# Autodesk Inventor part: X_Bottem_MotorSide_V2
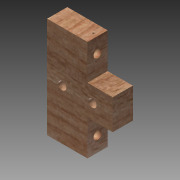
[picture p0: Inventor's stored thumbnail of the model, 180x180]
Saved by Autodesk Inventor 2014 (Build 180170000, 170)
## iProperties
Created: 2013-12
Part Number: X_Bottem_MotorSide_V2
Material: Birch
Document SubType Name: Modeling
Designer: Bram
Density: 0.512 g/cm^3
Appearance: Birch - Natural Medium Gloss
Author: Bram
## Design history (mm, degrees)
sketch "Sketch1"
  geometry: L1 (0, 0)-(60, 0); L2 (60, 0)-(60, 100); L3 (60, 100)-(0, 100); L4 (0, 100)-(0, 0); C1 r 4 at (15, 50); C2 r 4 at (45, 50)
  constraints: 8 end point, 2 centre point, 2 parallel, 1 horizontal, 1 perpendicular
  dimensions: "d0" = 60 distance of L3.end L2.end; "d1" = 100 distance of L2.end L1.end; "d4" = 8 diameter of C1; "d5" = 8 diameter of C2
extrude "Extrusion1" new body sketch "Sketch1" distance "d6" = 20; taper "d7" = 0 deg
sketch "Sketch2"
  geometry: L1 (0, 20)-(100, 20) reference; L2 (0, 0)-(0, 20) reference; L3 (50, 20)-(50, 10); L4 (50, 10)-(85, 10); L5 (50, 10)-(15, 10); C1 r 4 at (15, 10); C2 r 4 at (85, 10)
  constraints: 6 end point, 2 centre point, 2 coincident, 1 collinear, 1 midpoint, 1 parallel, 1 perpendicular
  dimensions: "d8" = 35 distance of L3.end L4.end; "d9" = 35 distance of L3.end L5.end; "d10" = 8 diameter of C1; "d11" = 8 diameter of C2
extrude "Extrusion2" cut sketch "Sketch2" distance "d12" = 80; taper "d13" = 0 deg
sketch "Sketch3"
  geometry: L1 (0, 0)-(100, 0) reference; L2 (100, 0)-(100, 20) reference; L3 (0, 20)-(100, 20) reference; L4 (0, 0)-(0, 20) reference; C1 r 4 at (15, 10) reference; C2 r 4 at (85, 10) reference
extrude "Extrusion3" join sketch "Sketch3" distance "d14" = 5; taper "d15" = 0 deg
sketch "Sketch4"
  geometry: L1 (5, 100)-(5, 0) reference; L2 (-60, 100)-(5, 100) reference; L3 (-60, 100)-(-20, 100); L4 (5, 50)-(-20, 50); L5 (-20, 50)-(-20, 80); L6 (-20, 50)-(-20, 20); L7 (-20, 20)-(5, 20); L8 (-20, 80)-(5, 80); L9 (-20, 80)-(5, 80); L10 (5, 80)-(5, 100); L11 (5, 100)-(-20, 100); L12 (-20, 100)-(-20, 80); L13 (-20, 20)-(5, 20); L14 (5, 20)-(5, 0); L15 (5, 0)-(-20, 0); L16 (-20, 0)-(-20, 20); 1 further point
  constraints: 28 end point, 5 parallel, 5 perpendicular, 3 point on line, 2 horizontal, 1 collinear, 1 midpoint
  dimensions: "d16" = 40 distance of L2.start L3.end; "d17" = 30 distance of L4.end L5.end; "d18" = 30 distance of L4.end L6.end
extrude "Extrusion4" cut sketch "Sketch4" distance "d19" = 20; taper "d20" = 0 deg
sketch "Sketch5"
  geometry: L1 (-20, 0)-(-60, 0) reference; L2 (-15, 50)-(-15, 65); L3 (-15, 50)-(-15, 35); L4 (-20, 20)-(-20, 35); L5 (-20, 35)-(5, 35); L6 (5, 35)-(5, 20); L7 (5, 20)-(-20, 20); L8 (-20, 20)-(-20, 35); L9 (-20, 80)-(-20, 65); L10 (-20, 65)-(5, 65); L11 (5, 65)-(5, 80); L12 (5, 80)-(-20, 80); L13 (-20, 80)-(-20, 65); C1 r 4 at (-15, 50) reference; 1 further point
  constraints: 24 end point, 7 equal length, 3 perpendicular, 2 horizontal
  dimensions: "d21" = 15 distance of L2.start L2.end; "d22" = 15 distance of L2.start L3.end
extrude "Extrusion5" cut sketch "Sketch5" distance "d23" = 20; taper "d24" = 0 deg
body "Solid1"
